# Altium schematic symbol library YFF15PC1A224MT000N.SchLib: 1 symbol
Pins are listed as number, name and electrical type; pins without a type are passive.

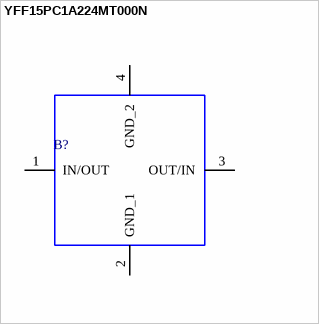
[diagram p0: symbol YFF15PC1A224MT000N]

## YFF15PC1A224MT000N
designator B?
3-terminal Filters, Insertion Loss=40dB (4MHz to 1000MHz), LxWxT: 1x0.55x0.3mm; Manufacturer_Name: TDK
footprint YFF15PC
pins: 1 IN/OUT, 2 GND_1, 3 OUT/IN, 4 GND_2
